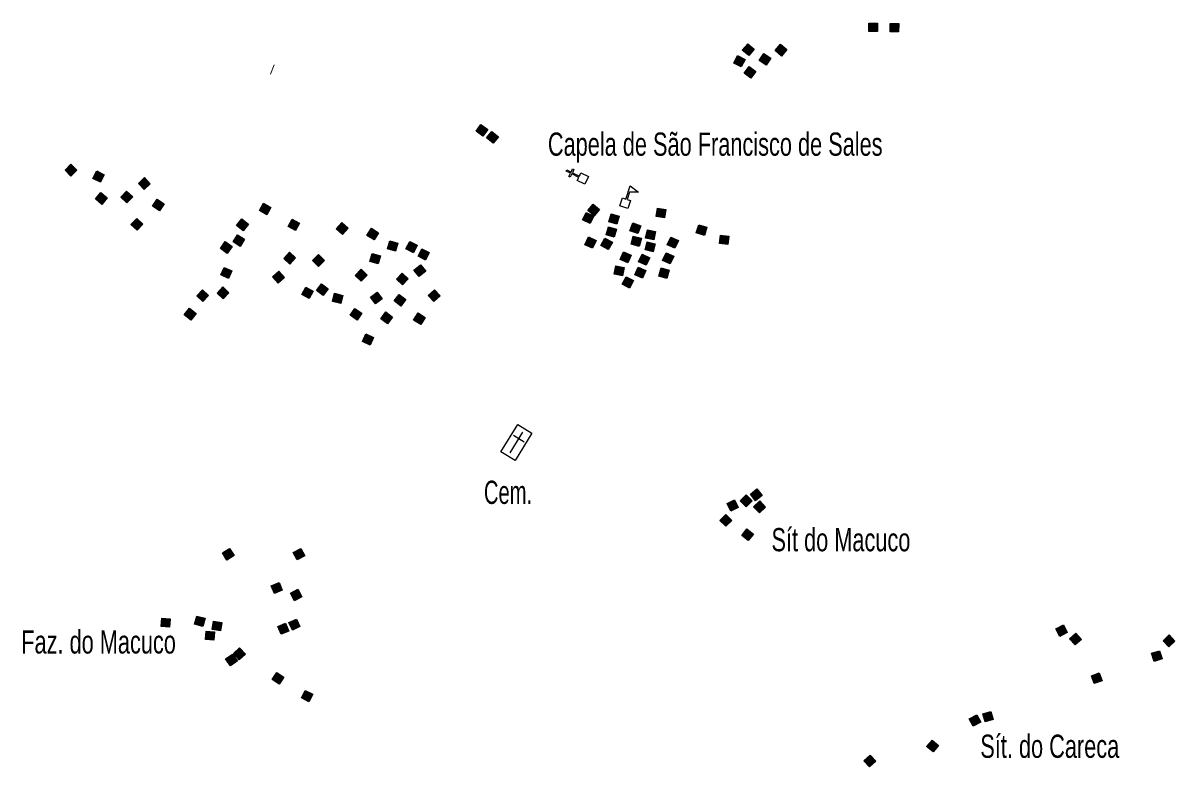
# Model space of a CAD drawing. Extents: x 679 to 705, y 7427.4 to 7455.4.
# Drawn here: x 683.916 to 687.885, y 7437.434 to 7439.997 of the extents above; entities that cross this region are included whole.
import ezdxf

# ---------------------------------------------------------------- set-up
doc = ezdxf.new("R2010")
doc.units = 0
doc.header["$LTSCALE"] = 0.032
for name, color, linetype, lineweight in [('2', 7, 'Continuous', 25), ('20', 7, 'Continuous', 25), ('4', 7, 'Continuous', 25), ('51', 7, 'Continuous', 13), ('6', 7, 'Continuous', 25)]:
    doc.layers.add(name, color=color, linetype=linetype, lineweight=lineweight)
doc.layers.add('61', color=7, linetype='Continuous')

msp = doc.modelspace()

# ---------------------------------------------------------------- hatches: boundary and pattern name
at = {"layer": '2'}
for points in [[(686.8591, 7439.9971), (686.8591, 7439.9681), (686.8301, 7439.9681), (686.8301, 7439.9971)], [(686.9326, 7439.9953), (686.9322, 7439.9663), (686.9033, 7439.9667), (686.9036, 7439.9957)], [(686.4123, 7439.9259), (686.4345, 7439.9072), (686.4158, 7439.885), (686.3936, 7439.9037)], [(686.5256, 7439.9243), (686.5477, 7439.9056), (686.529, 7439.8834), (686.5068, 7439.9021)], [(686.3777, 7439.8851), (686.4036, 7439.8719), (686.3904, 7439.846), (686.3645, 7439.8593)], [(686.4677, 7439.8921), (686.4917, 7439.8758), (686.4755, 7439.8518), (686.4515, 7439.8681)], [(686.4175, 7439.8476), (686.4408, 7439.8303), (686.4235, 7439.807), (686.4002, 7439.8243)], [(685.4935, 7439.6476), (685.5169, 7439.6306), (685.4999, 7439.6071), (685.4764, 7439.6241)], [(685.5314, 7439.6239), (685.5537, 7439.6053), (685.5351, 7439.583), (685.5129, 7439.6016)], [(684.1013, 7439.49), (684.0808, 7439.4695), (684.0603, 7439.49), (684.0807, 7439.5105)], [(684.1696, 7439.4873), (684.1955, 7439.4743), (684.1825, 7439.4484), (684.1566, 7439.4613)], [(684.3339, 7439.4644), (684.354, 7439.4435), (684.3331, 7439.4234), (684.313, 7439.4443)], [(684.1834, 7439.4133), (684.2058, 7439.3948), (684.1873, 7439.3724), (684.1649, 7439.3909)], [(684.2722, 7439.4181), (684.2935, 7439.3984), (684.2738, 7439.3772), (684.2525, 7439.3969)], [(684.3777, 7439.3906), (684.4017, 7439.3743), (684.3854, 7439.3504), (684.3614, 7439.3666)], [(684.7446, 7439.3759), (684.7698, 7439.3615), (684.7554, 7439.3364), (684.7302, 7439.3507)], [(685.8821, 7439.3318), (685.8691, 7439.3059), (685.8432, 7439.3188), (685.8562, 7439.3448)], [(685.9022, 7439.3546), (685.8836, 7439.3323), (685.8614, 7439.3508), (685.8799, 7439.3731)], [(686.1261, 7439.3261), (686.0974, 7439.33), (686.1012, 7439.3587), (686.13, 7439.3549)], [(684.3074, 7439.324), (684.3285, 7439.3041), (684.3087, 7439.283), (684.2875, 7439.3029)], [(684.6694, 7439.3223), (684.692, 7439.3042), (684.6739, 7439.2815), (684.6513, 7439.2996)], [(684.8433, 7439.3217), (684.8686, 7439.3074), (684.8543, 7439.2821), (684.8291, 7439.2964)], [(685.0137, 7439.3096), (685.0355, 7439.2905), (685.0164, 7439.2687), (684.9946, 7439.2878)], [(685.9699, 7439.3319), (685.9619, 7439.304), (685.934, 7439.3119), (685.942, 7439.3398)], [(686.0438, 7439.2988), (686.0341, 7439.2715), (686.0068, 7439.2813), (686.0165, 7439.3086)], [(684.6544, 7439.2676), (684.679, 7439.2523), (684.6636, 7439.2277), (684.6391, 7439.243)], [(685.116, 7439.29), (685.1405, 7439.2744), (685.1249, 7439.25), (685.1005, 7439.2655)], [(685.9606, 7439.2868), (685.9519, 7439.2591), (685.9242, 7439.2677), (685.9329, 7439.2954)], [(686.0951, 7439.2788), (686.0892, 7439.2504), (686.0608, 7439.2564), (686.0667, 7439.2848)], [(686.2714, 7439.2934), (686.263, 7439.2656), (686.2353, 7439.2739), (686.2436, 7439.3017)], [(686.3476, 7439.2627), (686.3442, 7439.2339), (686.3154, 7439.2372), (686.3188, 7439.266)], [(684.6126, 7439.244), (684.6362, 7439.227), (684.6192, 7439.2035), (684.5957, 7439.2204)], [(685.1795, 7439.2465), (685.2073, 7439.2384), (685.1993, 7439.2106), (685.1714, 7439.2187)], [(685.2485, 7439.2449), (685.2741, 7439.2313), (685.2605, 7439.2057), (685.2349, 7439.2193)], [(685.8898, 7439.248), (685.8779, 7439.2215), (685.8514, 7439.2334), (685.8634, 7439.2599)], [(685.9461, 7439.2418), (685.9322, 7439.2163), (685.9067, 7439.2303), (685.9207, 7439.2557)], [(686.0462, 7439.2556), (686.0388, 7439.2276), (686.0108, 7439.235), (686.0182, 7439.263)], [(686.0938, 7439.2368), (686.0871, 7439.2086), (686.0589, 7439.2154), (686.0656, 7439.2436)], [(686.1736, 7439.2481), (686.1618, 7439.2216), (686.1353, 7439.2333), (686.1471, 7439.2598)], [(684.8335, 7439.2075), (684.8547, 7439.1878), (684.835, 7439.1666), (684.8137, 7439.1863)], [(684.9335, 7439.1996), (684.9542, 7439.1793), (684.9339, 7439.1586), (684.9132, 7439.1789)], [(685.1188, 7439.2034), (685.1467, 7439.1954), (685.1387, 7439.1675), (685.1109, 7439.1755)], [(685.2895, 7439.2192), (685.3154, 7439.2063), (685.3025, 7439.1803), (685.2765, 7439.1933)], [(686.0109, 7439.197), (685.9992, 7439.1705), (685.9727, 7439.1823), (685.9844, 7439.2088)], [(686.0749, 7439.1886), (686.0624, 7439.1624), (686.0362, 7439.1748), (686.0487, 7439.201)], [(686.1577, 7439.1936), (686.1456, 7439.1672), (686.1193, 7439.1793), (686.1314, 7439.2057)], [(684.6091, 7439.1552), (684.6354, 7439.143), (684.6231, 7439.1167), (684.5969, 7439.129)], [(685.0801, 7439.1485), (685.1009, 7439.1283), (685.0807, 7439.1075), (685.0599, 7439.1277)], [(685.2846, 7439.1644), (685.3032, 7439.1421), (685.2809, 7439.1236), (685.2623, 7439.1459)], [(685.9865, 7439.1547), (685.9811, 7439.1262), (685.9526, 7439.1315), (685.958, 7439.16)], [(686.0618, 7439.1447), (686.0505, 7439.118), (686.0238, 7439.1293), (686.0351, 7439.156)], [(686.142, 7439.1453), (686.1343, 7439.1174), (686.1063, 7439.1251), (686.114, 7439.1531)], [(684.7968, 7439.1421), (684.8163, 7439.1207), (684.7949, 7439.1012), (684.7754, 7439.1226)], [(685.2216, 7439.1357), (685.2428, 7439.116), (685.2231, 7439.0948), (685.2018, 7439.1145)], [(686.0194, 7439.1095), (686.0057, 7439.0839), (685.9801, 7439.0976), (685.9938, 7439.1232)], [(684.5334, 7439.0783), (684.555, 7439.0589), (684.5356, 7439.0373), (684.514, 7439.0567)], [(684.6041, 7439.0879), (684.6251, 7439.0679), (684.6051, 7439.0469), (684.5841, 7439.0669)], [(684.8901, 7439.0871), (684.9155, 7439.073), (684.9014, 7439.0476), (684.876, 7439.0617)], [(684.9438, 7439.0989), (684.9669, 7439.0813), (684.9493, 7439.0582), (684.9263, 7439.0758)], [(685.1354, 7439.0702), (685.1532, 7439.0473), (685.1303, 7439.0295), (685.1125, 7439.0525)], [(685.3331, 7439.0783), (685.3527, 7439.0569), (685.3313, 7439.0374), (685.3118, 7439.0587)], [(684.9891, 7439.0659), (685.0173, 7439.0588), (685.0102, 7439.0307), (684.9821, 7439.0377)], [(685.2121, 7439.0622), (685.2348, 7439.0442), (685.2168, 7439.0215), (685.1941, 7439.0395)], [(684.4891, 7439.0143), (684.5119, 7438.9964), (684.4939, 7438.9736), (684.4711, 7438.9915)], [(685.0592, 7439.0141), (685.0832, 7438.9978), (685.0669, 7438.9738), (685.0429, 7438.9901)], [(685.1653, 7439.0015), (685.1885, 7438.9841), (685.1711, 7438.9609), (685.1479, 7438.9783)], [(685.2772, 7438.9981), (685.3016, 7438.9823), (685.2858, 7438.958), (685.2615, 7438.9737)], [(685.1234, 7438.9138), (685.1112, 7438.8875), (685.0849, 7438.8998), (685.0971, 7438.9261)], [(686.3671, 7438.3542), (686.38, 7438.3283), (686.3541, 7438.3153), (686.3411, 7438.3413)], [(686.4072, 7438.3711), (686.4277, 7438.3506), (686.4071, 7438.3301), (686.3866, 7438.3506)], [(686.4444, 7438.3917), (686.4625, 7438.369), (686.4398, 7438.351), (686.4217, 7438.3737)], [(686.4538, 7438.3503), (686.4739, 7438.3294), (686.4529, 7438.3093), (686.4329, 7438.3303)], [(686.337, 7438.3041), (686.3575, 7438.2836), (686.337, 7438.2631), (686.3165, 7438.2836)], [(686.4099, 7438.2545), (686.4324, 7438.2362), (686.4142, 7438.2137), (686.3917, 7438.2319)], [(684.6273, 7438.1867), (684.6426, 7438.1621), (684.618, 7438.1467), (684.6027, 7438.1713)], [(684.8723, 7438.1864), (684.8862, 7438.161), (684.8607, 7438.1471), (684.8469, 7438.1725)], [(684.7978, 7438.0693), (684.8088, 7438.0425), (684.782, 7438.0314), (684.771, 7438.0582)], [(684.8629, 7438.046), (684.8766, 7438.0205), (684.8511, 7438.0067), (684.8373, 7438.0323)], [(684.4225, 7437.9444), (684.4201, 7437.9155), (684.3912, 7437.9179), (684.3936, 7437.9468)], [(684.5426, 7437.9462), (684.5349, 7437.9183), (684.5069, 7437.926), (684.5147, 7437.954)], [(684.6004, 7437.9321), (684.596, 7437.9035), (684.5673, 7437.9079), (684.5717, 7437.9366)], [(684.82, 7437.9289), (684.8312, 7437.9022), (684.8045, 7437.891), (684.7932, 7437.9177)], [(684.8575, 7437.9436), (684.8698, 7437.9173), (684.8436, 7437.905), (684.8312, 7437.9312)], [(687.4999, 7437.9231), (687.5134, 7437.8974), (687.4877, 7437.8839), (687.4742, 7437.9096)], [(684.5755, 7437.8997), (684.5733, 7437.8708), (684.5444, 7437.8731), (684.5466, 7437.902)], [(687.5431, 7437.8951), (687.5623, 7437.8735), (687.5406, 7437.8542), (687.5214, 7437.8759)], [(687.8646, 7437.8888), (687.8845, 7437.8677), (687.8634, 7437.8478), (687.8435, 7437.8689)], [(684.6619, 7437.8441), (684.6816, 7437.8228), (684.6603, 7437.8031), (684.6406, 7437.8244)], [(684.6375, 7437.8231), (684.654, 7437.7993), (684.6302, 7437.7828), (684.6137, 7437.8066)], [(687.8318, 7437.8339), (687.8401, 7437.8062), (687.8123, 7437.7978), (687.804, 7437.8256)], [(684.7896, 7437.7591), (684.8138, 7437.7432), (684.7979, 7437.7189), (684.7737, 7437.7348)], [(687.6238, 7437.7577), (687.6332, 7437.7303), (687.6058, 7437.7209), (687.5964, 7437.7483)], [(684.8881, 7437.6979), (684.9138, 7437.6846), (684.9005, 7437.6588), (684.8748, 7437.6722)], [(687.2017, 7437.6136), (687.2152, 7437.5879), (687.1895, 7437.5744), (687.176, 7437.6001)], [(687.25, 7437.6248), (687.258, 7437.5969), (687.2301, 7437.589), (687.2221, 7437.6169)], [(687.0474, 7437.5265), (687.0698, 7437.5081), (687.0513, 7437.4857), (687.0289, 7437.5041)], [(686.8128, 7437.4555), (686.8344, 7437.4748), (686.8538, 7437.4533), (686.8322, 7437.4339)]]:
    msp.add_hatch(color=256, dxfattribs=at).paths.add_polyline_path(points)

# ---------------------------------------------------------------- linework, layer by layer
for points in [[(686.8591, 7439.9971), (686.8591, 7439.9681), (686.8301, 7439.9681), (686.8301, 7439.9971)], [(686.9326, 7439.9953), (686.9322, 7439.9663), (686.9033, 7439.9667), (686.9036, 7439.9957)], [(686.4123, 7439.9259), (686.4345, 7439.9072), (686.4158, 7439.885), (686.3936, 7439.9037)], [(686.5256, 7439.9243), (686.5477, 7439.9056), (686.529, 7439.8834), (686.5068, 7439.9021)], [(686.3777, 7439.8851), (686.4036, 7439.8719), (686.3904, 7439.846), (686.3645, 7439.8593)], [(686.4677, 7439.8921), (686.4917, 7439.8758), (686.4755, 7439.8518), (686.4515, 7439.8681)], [(686.4175, 7439.8476), (686.4408, 7439.8303), (686.4235, 7439.807), (686.4002, 7439.8243)], [(685.4935, 7439.6476), (685.5169, 7439.6306), (685.4999, 7439.6071), (685.4764, 7439.6241)], [(685.5314, 7439.6239), (685.5537, 7439.6053), (685.5351, 7439.583), (685.5129, 7439.6016)], [(684.1013, 7439.49), (684.0808, 7439.4695), (684.0603, 7439.49), (684.0807, 7439.5105)], [(684.1696, 7439.4873), (684.1955, 7439.4743), (684.1825, 7439.4484), (684.1566, 7439.4613)], [(684.3339, 7439.4644), (684.354, 7439.4435), (684.3331, 7439.4234), (684.313, 7439.4443)], [(684.1834, 7439.4133), (684.2058, 7439.3948), (684.1873, 7439.3724), (684.1649, 7439.3909)], [(684.2722, 7439.4181), (684.2935, 7439.3984), (684.2738, 7439.3772), (684.2525, 7439.3969)], [(684.3777, 7439.3906), (684.4017, 7439.3743), (684.3854, 7439.3504), (684.3614, 7439.3666)], [(684.7446, 7439.3759), (684.7698, 7439.3615), (684.7554, 7439.3364), (684.7302, 7439.3507)], [(685.8821, 7439.3318), (685.8691, 7439.3059), (685.8432, 7439.3188), (685.8562, 7439.3448)], [(685.9022, 7439.3546), (685.8836, 7439.3323), (685.8614, 7439.3508), (685.8799, 7439.3731)], [(686.1261, 7439.3261), (686.0974, 7439.33), (686.1012, 7439.3587), (686.13, 7439.3549)], [(684.3074, 7439.324), (684.3285, 7439.3041), (684.3087, 7439.283), (684.2875, 7439.3029)], [(684.6694, 7439.3223), (684.692, 7439.3042), (684.6739, 7439.2815), (684.6513, 7439.2996)], [(684.8433, 7439.3217), (684.8686, 7439.3074), (684.8543, 7439.2821), (684.8291, 7439.2964)], [(685.0137, 7439.3096), (685.0355, 7439.2905), (685.0164, 7439.2687), (684.9946, 7439.2878)], [(685.9699, 7439.3319), (685.9619, 7439.304), (685.934, 7439.3119), (685.942, 7439.3398)], [(686.0438, 7439.2988), (686.0341, 7439.2715), (686.0068, 7439.2813), (686.0165, 7439.3086)], [(684.6544, 7439.2676), (684.679, 7439.2523), (684.6636, 7439.2277), (684.6391, 7439.243)], [(685.116, 7439.29), (685.1405, 7439.2744), (685.1249, 7439.25), (685.1005, 7439.2655)], [(685.9606, 7439.2868), (685.9519, 7439.2591), (685.9242, 7439.2677), (685.9329, 7439.2954)], [(686.0951, 7439.2788), (686.0892, 7439.2504), (686.0608, 7439.2564), (686.0667, 7439.2848)], [(686.2714, 7439.2934), (686.263, 7439.2656), (686.2353, 7439.2739), (686.2436, 7439.3017)], [(686.3476, 7439.2627), (686.3442, 7439.2339), (686.3154, 7439.2372), (686.3188, 7439.266)], [(684.6126, 7439.244), (684.6362, 7439.227), (684.6192, 7439.2035), (684.5957, 7439.2204)], [(685.1795, 7439.2465), (685.2073, 7439.2384), (685.1993, 7439.2106), (685.1714, 7439.2187)], [(685.2485, 7439.2449), (685.2741, 7439.2313), (685.2605, 7439.2057), (685.2349, 7439.2193)], [(685.8898, 7439.248), (685.8779, 7439.2215), (685.8514, 7439.2334), (685.8634, 7439.2599)], [(685.9461, 7439.2418), (685.9322, 7439.2163), (685.9067, 7439.2303), (685.9207, 7439.2557)], [(686.0462, 7439.2556), (686.0388, 7439.2276), (686.0108, 7439.235), (686.0182, 7439.263)], [(686.0938, 7439.2368), (686.0871, 7439.2086), (686.0589, 7439.2154), (686.0656, 7439.2436)], [(686.1736, 7439.2481), (686.1618, 7439.2216), (686.1353, 7439.2333), (686.1471, 7439.2598)], [(684.8335, 7439.2075), (684.8547, 7439.1878), (684.835, 7439.1666), (684.8137, 7439.1863)], [(684.9335, 7439.1996), (684.9542, 7439.1793), (684.9339, 7439.1586), (684.9132, 7439.1789)], [(685.1188, 7439.2034), (685.1467, 7439.1954), (685.1387, 7439.1675), (685.1109, 7439.1755)], [(685.2895, 7439.2192), (685.3154, 7439.2063), (685.3025, 7439.1803), (685.2765, 7439.1933)], [(686.0109, 7439.197), (685.9992, 7439.1705), (685.9727, 7439.1823), (685.9844, 7439.2088)], [(686.0749, 7439.1886), (686.0624, 7439.1624), (686.0362, 7439.1748), (686.0487, 7439.201)], [(686.1577, 7439.1936), (686.1456, 7439.1672), (686.1193, 7439.1793), (686.1314, 7439.2057)], [(684.6091, 7439.1552), (684.6354, 7439.143), (684.6231, 7439.1167), (684.5969, 7439.129)], [(685.0801, 7439.1485), (685.1009, 7439.1283), (685.0807, 7439.1075), (685.0599, 7439.1277)], [(685.2846, 7439.1644), (685.3032, 7439.1421), (685.2809, 7439.1236), (685.2623, 7439.1459)], [(685.9865, 7439.1547), (685.9811, 7439.1262), (685.9526, 7439.1315), (685.958, 7439.16)], [(686.0618, 7439.1447), (686.0505, 7439.118), (686.0238, 7439.1293), (686.0351, 7439.156)], [(686.142, 7439.1453), (686.1343, 7439.1174), (686.1063, 7439.1251), (686.114, 7439.1531)], [(684.7968, 7439.1421), (684.8163, 7439.1207), (684.7949, 7439.1012), (684.7754, 7439.1226)], [(685.2216, 7439.1357), (685.2428, 7439.116), (685.2231, 7439.0948), (685.2018, 7439.1145)], [(686.0194, 7439.1095), (686.0057, 7439.0839), (685.9801, 7439.0976), (685.9938, 7439.1232)], [(684.5334, 7439.0783), (684.555, 7439.0589), (684.5356, 7439.0373), (684.514, 7439.0567)], [(684.6041, 7439.0879), (684.6251, 7439.0679), (684.6051, 7439.0469), (684.5841, 7439.0669)], [(684.8901, 7439.0871), (684.9155, 7439.073), (684.9014, 7439.0476), (684.876, 7439.0617)], [(684.9438, 7439.0989), (684.9669, 7439.0813), (684.9493, 7439.0582), (684.9263, 7439.0758)], [(685.1354, 7439.0702), (685.1532, 7439.0473), (685.1303, 7439.0295), (685.1125, 7439.0525)], [(685.3331, 7439.0783), (685.3527, 7439.0569), (685.3313, 7439.0374), (685.3118, 7439.0587)], [(684.9891, 7439.0659), (685.0173, 7439.0588), (685.0102, 7439.0307), (684.9821, 7439.0377)], [(685.2121, 7439.0622), (685.2348, 7439.0442), (685.2168, 7439.0215), (685.1941, 7439.0395)], [(684.4891, 7439.0143), (684.5119, 7438.9964), (684.4939, 7438.9736), (684.4711, 7438.9915)], [(685.0592, 7439.0141), (685.0832, 7438.9978), (685.0669, 7438.9738), (685.0429, 7438.9901)], [(685.1653, 7439.0015), (685.1885, 7438.9841), (685.1711, 7438.9609), (685.1479, 7438.9783)], [(685.2772, 7438.9981), (685.3016, 7438.9823), (685.2858, 7438.958), (685.2615, 7438.9737)], [(685.1234, 7438.9138), (685.1112, 7438.8875), (685.0849, 7438.8998), (685.0971, 7438.9261)], [(686.3671, 7438.3542), (686.38, 7438.3283), (686.3541, 7438.3153), (686.3411, 7438.3413)], [(686.4072, 7438.3711), (686.4277, 7438.3506), (686.4071, 7438.3301), (686.3866, 7438.3506)], [(686.4444, 7438.3917), (686.4625, 7438.369), (686.4398, 7438.351), (686.4217, 7438.3737)], [(686.4538, 7438.3503), (686.4739, 7438.3294), (686.4529, 7438.3093), (686.4329, 7438.3303)], [(686.337, 7438.3041), (686.3575, 7438.2836), (686.337, 7438.2631), (686.3165, 7438.2836)], [(686.4099, 7438.2545), (686.4324, 7438.2362), (686.4142, 7438.2137), (686.3917, 7438.2319)], [(684.6273, 7438.1867), (684.6426, 7438.1621), (684.618, 7438.1467), (684.6027, 7438.1713)], [(684.8723, 7438.1864), (684.8862, 7438.161), (684.8607, 7438.1471), (684.8469, 7438.1725)], [(684.7978, 7438.0693), (684.8088, 7438.0425), (684.782, 7438.0314), (684.771, 7438.0582)], [(684.8629, 7438.046), (684.8766, 7438.0205), (684.8511, 7438.0067), (684.8373, 7438.0323)], [(684.4225, 7437.9444), (684.4201, 7437.9155), (684.3912, 7437.9179), (684.3936, 7437.9468)], [(684.5426, 7437.9462), (684.5349, 7437.9183), (684.5069, 7437.926), (684.5147, 7437.954)], [(684.6004, 7437.9321), (684.596, 7437.9035), (684.5673, 7437.9079), (684.5717, 7437.9366)], [(684.82, 7437.9289), (684.8312, 7437.9022), (684.8045, 7437.891), (684.7932, 7437.9177)], [(684.8575, 7437.9436), (684.8698, 7437.9173), (684.8436, 7437.905), (684.8312, 7437.9312)], [(687.4999, 7437.9231), (687.5134, 7437.8974), (687.4877, 7437.8839), (687.4742, 7437.9096)], [(684.5755, 7437.8997), (684.5733, 7437.8708), (684.5444, 7437.8731), (684.5466, 7437.902)], [(687.5431, 7437.8951), (687.5623, 7437.8735), (687.5406, 7437.8542), (687.5214, 7437.8759)], [(687.8646, 7437.8888), (687.8845, 7437.8677), (687.8634, 7437.8478), (687.8435, 7437.8689)], [(684.6619, 7437.8441), (684.6816, 7437.8228), (684.6603, 7437.8031), (684.6406, 7437.8244)], [(684.6375, 7437.8231), (684.654, 7437.7993), (684.6302, 7437.7828), (684.6137, 7437.8066)], [(687.8318, 7437.8339), (687.8401, 7437.8062), (687.8123, 7437.7978), (687.804, 7437.8256)], [(684.7896, 7437.7591), (684.8138, 7437.7432), (684.7979, 7437.7189), (684.7737, 7437.7348)], [(687.6238, 7437.7577), (687.6332, 7437.7303), (687.6058, 7437.7209), (687.5964, 7437.7483)], [(684.8881, 7437.6979), (684.9138, 7437.6846), (684.9005, 7437.6588), (684.8748, 7437.6722)], [(687.2017, 7437.6136), (687.2152, 7437.5879), (687.1895, 7437.5744), (687.176, 7437.6001)], [(687.25, 7437.6248), (687.258, 7437.5969), (687.2301, 7437.589), (687.2221, 7437.6169)], [(687.0474, 7437.5265), (687.0698, 7437.5081), (687.0513, 7437.4857), (687.0289, 7437.5041)], [(686.8128, 7437.4555), (686.8344, 7437.4748), (686.8538, 7437.4533), (686.8322, 7437.4339)]]:
    msp.add_lwpolyline(points, close=True, dxfattribs=at)
at = {"layer": '20'}
for p, q in [((685.5942, 7438.5162), (685.6378, 7438.5876)), ((685.606, 7438.5769), (685.6424, 7438.5547))]:
    msp.add_line(p, q, dxfattribs=at)
msp.add_lwpolyline([(685.6199, 7438.6134), (685.6685, 7438.5837), (685.611, 7438.4896), (685.5624, 7438.5192)], close=True, dxfattribs=at)
at = {"layer": '4'}
for points in [[(685.9924, 7439.3906), (686.0077, 7439.4365), (686.0362, 7439.4147), (686.0053, 7439.4138), (685.997, 7439.389)], [(685.997, 7439.389), (686.0085, 7439.3852), (685.9993, 7439.3577), (685.9718, 7439.3668), (685.981, 7439.3944), (685.9924, 7439.3906)]]:
    msp.add_lwpolyline(points, dxfattribs=at)
at = {"layer": '51'}
msp.add_line((684.7688, 7439.8215), (684.7814, 7439.853), dxfattribs=at)
at = {"layer": '6'}
for points in [[(685.8306, 7439.4653), (685.8063, 7439.4771), (685.801, 7439.4662), (685.7966, 7439.4684), (685.8018, 7439.4793), (685.7871, 7439.4864), (685.7892, 7439.4908), (685.8039, 7439.4836), (685.8092, 7439.4945), (685.8136, 7439.4923), (685.8084, 7439.4814), (685.8327, 7439.4696)], [(685.8327, 7439.4696), (685.838, 7439.4805), (685.8641, 7439.4678), (685.8514, 7439.4417), (685.8253, 7439.4544), (685.8306, 7439.4653)]]:
    msp.add_lwpolyline(points, dxfattribs=at)

# ---------------------------------------------------------------- texts
at = {"layer": '61'}
for s, width, p in [('Capela de São Francisco de Sales', 0.7, (685.724, 7439.5399)), ('Cem.', 0.65, (685.5036, 7438.3403)), ('Sít do Macuco', 0.7, (686.4943, 7438.177)), ('Faz. do Macuco', 0.7, (683.9095, 7437.8247)), ('Sít. do Careca', 0.7, (687.2138, 7437.4653))]:
    msp.add_text(s, height=0.08, dxfattribs=dict(at, width=width)).set_placement(p)

doc.saveas('drawing.dxf')
